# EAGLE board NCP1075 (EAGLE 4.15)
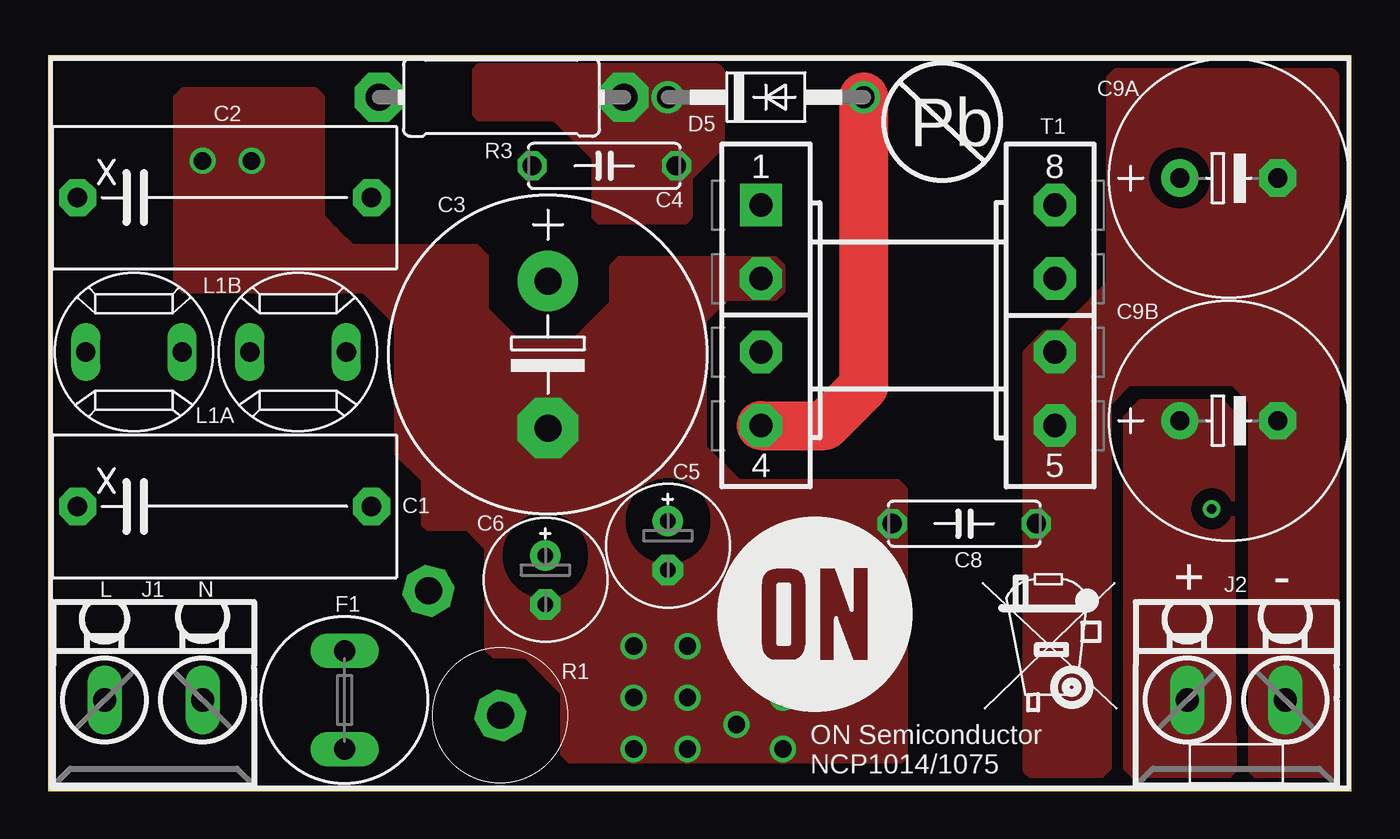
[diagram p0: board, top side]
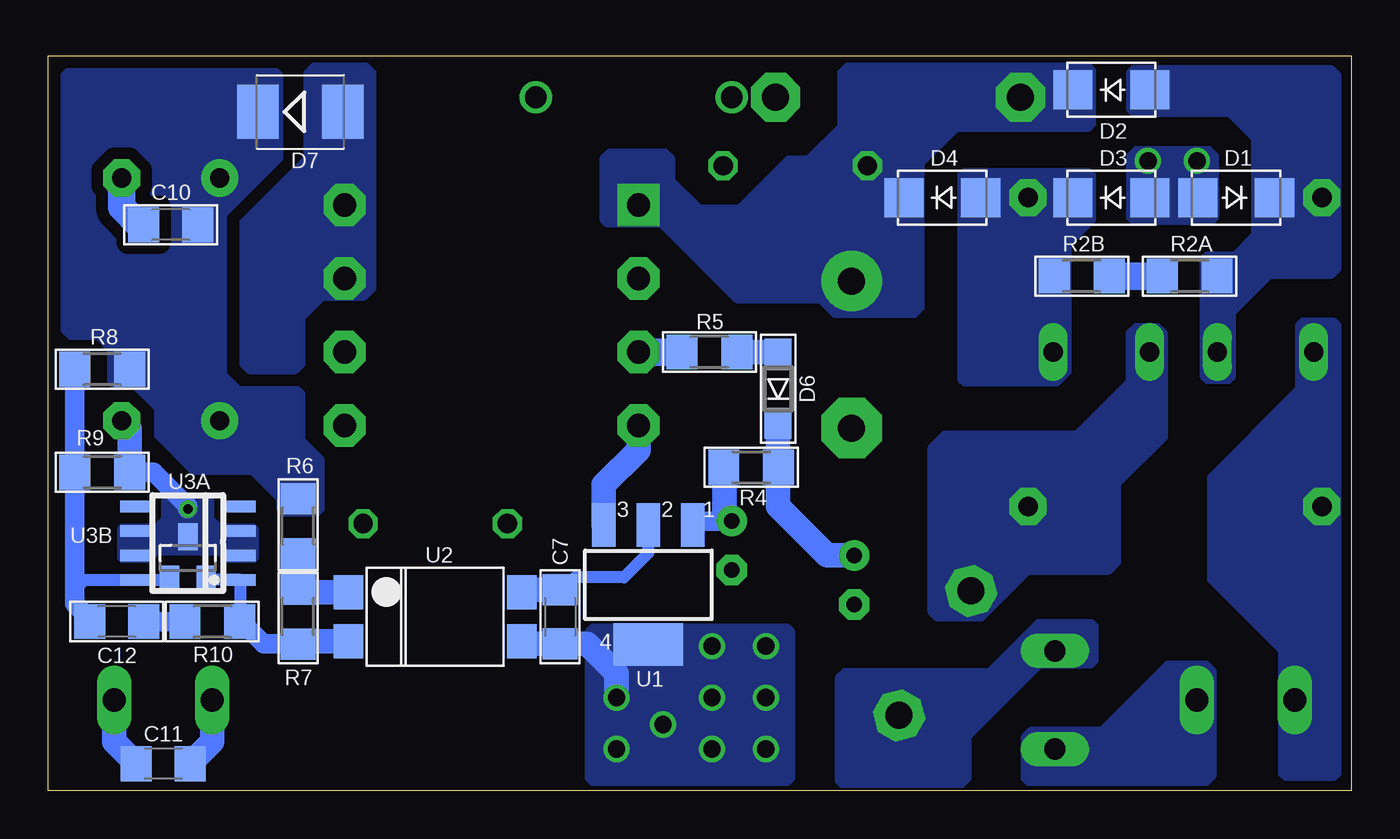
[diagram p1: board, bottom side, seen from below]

Size 67.56 x 38.1 mm. Coordinates in mm from the lower left corner, seen from the top.
Outline: 0,0 67.56,0 67.56,38.1 0,38.1 0,0
Copper layers (1*16): Top 0.035mm / dielectric 1.5mm / Bottom 0.035mm
Design rules "default": minimum track width 10mil, minimum drill 19mil, track to track 8mil, track to pad 8mil, pad to pad 8mil, via to via 8mil, smd to smd 8mil, copper to edge 5mil, drill to drill 8mil, minimum pad ring 10mil, minimum via ring 8mil, stop-mask expansion 4mil, vias tented up to drill 0mil, thermal gap 10mil

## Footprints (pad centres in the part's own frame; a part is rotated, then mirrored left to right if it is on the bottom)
XC18B7.5LS15 = drill 1.016 pad 1.93 octagon: 1 -7.62,0; 2 7.62,0
E7,5-16 = drill 1.4 pad 3.15 round: + -3.81,0 | drill 1.4 pad 3.15 octagon: - 3.81,0
C075-025X080 = drill 1 octagon: 1 -3.74,0; 2 3.74,0
E2.5-6.5 = drill 0.813 pad 1.575 round: + -1.27,0 | drill 0.813 pad 1.575 octagon: - 1.27,0
C1206 = smd 1.6 x 1.8: 1 -1.4,0; 2 1.4,0
E5-12,5 = drill 1 pad 1.93 round: + -2.54,0 | drill 1 pad 1.93 octagon: - 2.54,0
SMA-DIODE = smd 2.032 x 2.032: A 1.994,0; C -1.994,0
DO41-10 = drill 1.118 round: A 5.08,0; C -5.08,0
SOD123 = smd 1.4 x 1.4: A 1.9,0; C -1.9,0
SMB = smd 2.159 x 2.794: A 2.2,0; C -2.2,0
TR5 = drill 1.1 pad 1.778 long: 1 -2.54,0; 2 2.54,0
2-PIN = drill 1.2 long: + -2.54,0; - 2.54,0
WE-7447728215 = drill 1 long: P$1 -2.5,0; P$2 2.5,0
3W-STAND-UP = drill 1.4 pad 2.54 octagon: P$1 3.75,0; P$2 -3.71,0
R1206 = smd 1.6 x 1.803: 1 -1.422,0; 2 1.422,0
0411/12 = drill 1.4 pad 2.54 octagon: 1 -6.35,0; 2 6.35,0
E_16/8/5-EF_16-HORIZONTAL = drill 1.2 pad 2.184 square: 1 -7.62,5.715 | drill 1.2 pad 2.184 octagon: 2 -7.62,1.905; 3 -7.62,-1.905; 4 -7.62,-5.715; 5 7.62,-5.715; 6 7.62,-1.905; 7 7.62,1.905; 8 7.62,5.715
SOT-223 = smd 1.219 x 2.235: 1 -2.311,-3.099; 2 0,-3.099; 3 2.311,-3.099 | smd 3.6 x 2.2: 4 0,3.099
4PIN-SURFMOUNT-OPTO = smd 1.524 x 1.778: 1 4.496,-1.27; 2 4.496,1.27; 3 -4.496,1.27; 4 -4.496,-1.27
SOT-23 = smd 1 x 1.4: 1 -0.95,-1.1; 2 0.95,-1.1; 3 0,1.1
SOIC-8 = smd 0.61 x 1.524: 1 -1.905,-2.743; 2 -0.635,-2.743; 3 0.635,-2.743; 4 1.905,-2.743; 5 1.905,2.743; 6 0.635,2.743; 7 -0.635,2.743; 8 -1.905,2.743

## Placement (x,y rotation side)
C1  100nF  [XC18B7.5LS15]  9.14,14.73 0 top
C2  100nF  [XC18B7.5LS15]  9.14,30.73 0 top
C3  22uF  [E7,5-16]  25.91,22.61 270 top
C4  1nF  [C075-025X080]  28.83,32.39 0 top
C5  22uF  [E2.5-6.5]  32.13,12.7 270 top
C6  4.7uF  [E2.5-6.5]  25.78,10.92 270 top
C7  1nF  [C1206]  41.02,9.02 270 bottom
C8  1nF  [C075-025X080]  47.5,13.84 0 top
C9A  1000uF  [E5-12,5]  61.21,31.75 0 top
C9B  1000uF  [E5-12,5]  61.21,19.18 0 top
C10  100nF  [C1206]  61.21,29.34 180 bottom
C11  100nF  [C1206]  61.6,1.4 180 bottom
C12  100nF  [C1206]  64.01,8.76 180 bottom
D1  MRA4007  [SMA-DIODE]  5.97,30.73 180 bottom
D2  MRA4007  [SMA-DIODE]  12.45,36.32 0 bottom
D3  MRA4007  [SMA-DIODE]  12.45,30.73 0 bottom
D4  MRA4007  [SMA-DIODE]  21.21,30.73 0 bottom
D5  1N4937  [DO41-10]  37.21,35.94 0 top
D6  MMSD4148A  [SOD123]  29.72,20.83 90 bottom
D7  MBRS260T3  [SMB]  54.48,35.18 0 bottom
E$2  [ON2]  39.76,9.15 0 top
F1  1.5A  [TR5]  15.37,4.7 90 top
J1  [2-PIN]  5.46,4.7 0 top
J2  [2-PIN]  61.6,4.7 0 top
L1A  1mH  [WE-7447728215]  4.45,22.73 0 top
L1B  1mH  [WE-7447728215]  12.95,22.73 0 top
R1  4.3/3W  [3W-STAND-UP]  21.59,7.11 120 top
R2A  1M  [R1206]  8.38,26.67 0 bottom
R2B  1M  [R1206]  13.97,26.67 0 bottom
R3  68K  [0411/12]  23.5,35.94 180 top
R4  1K  [R1206]  31.12,16.76 180 bottom
R5  10  [R1206]  33.27,22.73 0 bottom
R6  1K  [R1206]  54.61,13.72 270 bottom
R7  1K  [R1206]  54.61,9.02 270 bottom
R8  39K  [R1206]  64.77,21.84 0 bottom
R9  10K  [R1206]  64.77,16.51 180 bottom
R10  10K  [R1206]  59.06,8.76 0 bottom
T1  [E_16/8/5-EF_16-HORIZONTAL]  44.58,24.64 0 top
U1  NCP1075  [SOT-223]  36.45,10.67 180 bottom
U2  PS2561L_1  [4PIN-SURFMOUNT-OPTO]  47.5,9.02 180 bottom
U3A  NCP431A  [SOT-23]  60.33,12.07 0 bottom
U3B  NCP431A  [SOIC-8]  60.33,12.83 90 bottom
U$3  [WEEE_SMALL]  52.07,5.46 0 top

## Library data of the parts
C1-C8 C9A C9B C10-C12 R2A R2B R3-R10 = rcl
D1-D7 = diode
E$2 = loga
F1 = fuse
J1 J2 = My CONNECTOR lib
L1A L1B = MY  INDUCTOR Lib
R1 = resistor-power
T1 = My X-former
U1 U3A U3B = My IC Lib
U2 = optocoupler
U$3 = My Sign Lib

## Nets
N$1: C1.1 J1.+ L1A.P$1
N$2: F1.1 J1.-
N$3: C2.1 D1.C D2.A L1A.P$2 R2A.2
N$4: C1.2 L1B.P$1 R1.P$1
N$5: F1.2 R1.P$2
N$6: C2.2 D3.C D4.A L1B.P$2 R2B.1
N$7: R2A.1 R2B.2
N$9: D5.A T1.4 U1.3
N$10: C3.+ C4.1 D2.C D4.C R3.2 T1.1
N$11: C4.2 D5.C R3.1
N$13: C5.+ R4.2 U1.1
N$14: C12.1 R10.1
N$15: R7.2 R10.2 U2.2 U3A.2 U3B.1
N$18: R5.1 T1.3
N$19: D6.A R5.2
N$20: C6.+ D6.C R4.1
N$21: C7.1 U1.2 U2.4
N$23: R6.2 R7.1 U2.1
N$24: C12.2 R8.1 R9.2 U3A.1 U3B.8
N$25: D7.A T1.7 T1.8
N$28: C8.2 C9A.- C9B.- C10.2 C11.2 J2.- R9.1 T1.5 T1.6 U3A.3 U3B.2 U3B.3 U3B.6 U3B.7
N$30: C9A.+ C9B.+ C10.1 C11.1 D7.C J2.+ R6.1 R8.2
N$44: C3.- C5.- C6.- C7.2 C8.1 D1.A D3.A T1.2 U1.4 U2.3

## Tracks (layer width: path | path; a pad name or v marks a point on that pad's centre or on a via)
N$1
  pour Bottom (no thermals): 3.68,7.24 3.68,0.89 3.43,0.64 0.89,0.64 0.64,0.89 0.64,24.13 0.89,24.38 2.54,24.38 2.79,24.13 2.79,20.83 7.37,16.26 7.37,10.92
N$2
  pour Bottom (no thermals): 7.49,6.6 9.53,6.6 12.95,3.18 16.64,3.18 17.02,2.79 17.02,0.64 16.76,0.38 7.49,0.38 7.11,0.76 7.11,6.22
N$3
  pour Bottom (no thermals): 6.1,21.46 6.1,24.77 4.19,26.67 1.02,26.67 0.64,27.05 0.64,37.08 1.02,37.47 11.3,37.47 11.56,37.21 11.56,35.31 11.3,35.05 6.35,35.05 5.08,33.78 5.08,28.83 6.1,27.81 7.49,27.81 7.75,27.56 7.75,21.46 7.49,21.21 6.35,21.21
N$4
  pour Bottom (no thermals): 16.76,11.3 19.18,8.89 21.46,8.89 21.84,9.27 21.84,17.78 21.08,18.54 14.22,18.54 11.56,21.21 11.56,23.75 11.18,24.13 10.03,24.13 9.65,23.75 9.65,18.29 12.07,15.88 12.07,11.81 12.57,11.3
N$5
  pour Bottom (no thermals): 13.21,6.73 13.21,8.51 13.46,8.76 16.26,8.76 18.8,6.22 26.29,6.22 26.67,5.84 26.67,0.51 26.42,0.25 20.19,0.25 19.81,0.64 19.81,2.79 16.13,6.48 13.46,6.48
N$6
  pour Bottom (no thermals): 14.61,22.73 14.61,28.32 13.34,29.59 13.34,31.88 13.59,32.13 20.07,32.13 20.32,31.88 20.32,21.34 20.07,21.08 15.24,21.08 14.61,21.72
N$7
  Bottom 1.422: R2A.1 R2B.2
N$9
  Top 2.54: D5.A 42.29,20.96 40.26,18.92 T1.4
  Bottom 1.27: U1.3 38.76,15.85 36.96,17.65 T1.4
N$10
  pour Bottom (no thermals): 13.59,37.59 26.16,37.59 26.54,37.21 26.54,34.42 28.19,32.77 29.21,32.77 31.75,30.23 33.78,30.23 35.18,31.62 35.18,32.77 35.56,33.15 38.48,33.15 38.86,32.77 38.86,29.59 38.61,29.34 35.81,29.34 31.88,25.4 27.56,25.4 26.8,24.64 22.61,24.64 22.23,25.02 22.23,32.51 20.45,34.29 13.59,34.29 13.34,34.54 13.34,37.34
N$11
  pour Top (no thermals): 22.35,37.59 34.67,37.59 34.93,37.34 34.93,33.4 33.27,31.75 33.27,29.72 33.02,29.46 28.58,29.46 28.32,29.72 28.32,32.77 26.29,34.8 22.35,34.8 22.1,35.05 22.1,37.34
N$13
  Bottom 1.016: U1.1 33.93,13.97 C5.+
  Bottom 1.27: C5.+ 32.51,14.35 32.51,16.76 R4.2
N$14
  Bottom 1.016: C12.1 R10.1
N$15
  Bottom 0.61: U3A.2 59.35,10.97 59.31,10.92 U3B.1 57.58,8.84 57.66,8.76 R10.2
  Bottom 1.016: R10.2 57.53,8.76 56.39,7.62 54.61,7.62
  Bottom 1.27: R7.2 54.61,7.62 54.48,7.75 U2.2
N$18
  Bottom 1.422: R5.1 T1.3
N$19
  Bottom 1.27: D6.A R5.2
N$20
  Bottom 1.27: D6.C 29.72,16.79 R4.1 29.69,16.66 29.72,16.64 29.72,14.73 27.18,12.19 C6.+
N$21
  Bottom 0.61: U1.2 36.45,12.32 37.72,11.05 40.26,11.05 41.02,10.29 C7.1
  Bottom 1.27: U2.4 42.93,10.29 42.8,10.42 C7.1
N$23
  Bottom 1.016: 54.61,10.41 R7.1
  Bottom 1.27: U2.1 54.48,10.29 54.61,10.41 | 54.61,12.32 R6.2 R7.1
N$24
  Bottom 0.61: U3A.1 61.3,10.97 61.34,10.92 U3B.8 65.66,10.92 66.17,10.41 66.19,10.41
  Bottom 1.016: R8.1 66.19,16.54 66.17,16.51 R9.2 66.19,10.41 66.19,9.68 65.41,8.89 C12.2
N$25
  pour Bottom (no thermals): 50.67,26.04 50.67,37.21 51.05,37.59 53.85,37.59 54.23,37.21 54.23,32.77 57.53,29.46 57.53,22.1 57.15,21.72 54.74,21.72 54.36,22.1 54.36,24.51 53.34,25.53 51.18,25.53
N$28  (via drill 0.5)
  Bottom 1.016: v60.33,14.61 60.33,14.73 62.1,16.51 R9.1 63.37,16.51
  Bottom 1.27: C11.2 64.14,2.54 J2.- | R9.1 63.35,18.77 C9B.-
  Bottom 1.422: C10.2 62.87,29.34 63.75,30.23 C9A.-
  pour Bottom (no thermals): 56.77,12.07 56.77,13.59 56.9,13.72 58.67,13.72 59.06,14.1 59.06,14.99 59.18,15.11 61.47,15.11 61.6,14.99 61.6,14.1 61.98,13.72 63.75,13.72 63.88,13.59 63.88,12.07 63.75,11.94 62.36,11.94 61.98,12.32 58.67,12.32 58.29,11.94 56.9,11.94
  pour Top (isolate 0.61, no thermals): 50.67,22.73 51.69,23.75 52.45,23.75 54.99,26.29 54.99,36.96 55.37,37.34 66.55,37.34 66.8,37.08 66.8,1.02 66.55,0.76 62.61,0.76 62.36,1.02 62.36,20.19 61.47,21.08 56.01,21.08 54.99,20.07 54.99,1.14 54.61,0.76 50.93,0.76 50.67,1.02
N$30
  Bottom 1.27: C11.1 59.06,2.54 J2.+
  pour Bottom (isolate 0.61, no thermals): 55.75,37.34 66.55,37.34 66.8,37.08 66.8,23.88 66.42,23.5 65.02,23.5 64.39,22.86 64.39,21.21 64.14,20.96 63.12,20.96 61.98,19.81 61.98,18.42 60.07,16.51 57.02,16.51 55.63,15.11 55.63,14.61 55.37,14.35 53.59,14.35 53.34,14.61 53.34,17.15 54.36,18.16 54.36,20.57 54.61,20.83 57.66,20.83 58.42,21.59 58.42,29.85 55.5,32.77 55.5,37.08
  pour Top (isolate 0.61, rank 2, no thermals): 61.21,0.76 56.26,0.76 55.88,1.14 55.88,19.81 56.26,20.19 60.96,20.19 61.34,19.81 61.47,1.02
N$44  (via drill 0.9)
  Bottom 1.27: U2.3 42.93,7.75 42.8,7.62 C7.2 39.62,7.62 38.1,6.1 v38.1,4.83
  other vias: 8,32.64 10.54,32.64 30.35,7.49 30.35,4.83 33.15,4.83 30.35,2.16 33.15,2.16 33.15,7.49 38.1,2.16 35.69,3.43
  pour Bottom (no thermals): 6.99,29.85 6.99,32.89 7.37,33.27 11.18,33.27 11.56,32.89 11.56,29.72 11.3,29.46 7.24,29.46 6.99,29.72 6.99,31.24
  pour Bottom (no thermals): 34.04,8.51 39.37,8.51 39.62,8.26 39.62,0.64 39.37,0.38 29.21,0.38 28.96,0.64 28.96,8.26 29.21,8.51
  pour Top (isolate 1.422, no thermals): 6.6,35.94 6.6,26.29 6.99,25.91 16.38,25.91 18.03,24.26 18.03,17.53 19.43,16.13 19.43,13.84 19.69,13.59 21.72,13.59 22.73,12.57 22.73,7.37 23.11,6.99 24.77,6.99 26.67,5.08 26.67,1.91 27.05,1.52 44.2,1.52 44.45,1.78 44.45,15.62 44.07,16 35.81,16 34.04,17.78 34.04,24.38 35.18,25.53 37.72,25.53 38.1,25.91 38.1,27.18 37.72,27.56 29.59,27.56 29.21,27.18 29.21,25.27 27.18,23.24 24.38,23.24 22.73,24.89 22.73,27.69 22.23,28.19 15.75,28.19 14.22,29.72 14.22,35.94 13.84,36.32 6.99,36.32

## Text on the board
tPlace: Pb | L | N | + | - | ON Semiconductor | NCP1014/1075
